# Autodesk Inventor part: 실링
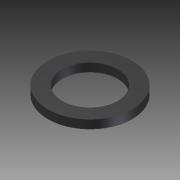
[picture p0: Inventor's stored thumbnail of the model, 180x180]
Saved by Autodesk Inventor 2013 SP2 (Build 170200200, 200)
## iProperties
Created: 2025-04
Part Number: 실링
Material: Generic
Document SubType Name: Modeling
Designer: 601
Density: 1 g/cm^3
Author: 601
변환 표준: STEP AP214IS
전처리기: Build: 200, Release: 2013 SP2 Update 6 - Date: Thu 07/17/2014
전송 단위: 밀리미터
불확실성: 0.01
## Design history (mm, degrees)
node "실링1"
node "솔리드1"
node "기준1"
